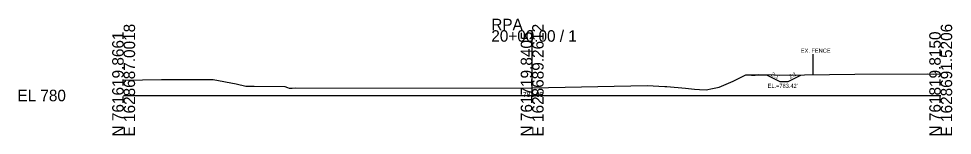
# Model space of a CAD drawing. Extents: x -26 to 203, y 990 to 7517.
# Drawn here: x -25.7 to 202.8, y 3990.3 to 4018.7 of the extents above; entities that cross this region are included whole.
import ezdxf

# ---------------------------------------------------------------- set-up
doc = ezdxf.new("R2010")
doc.units = 0
for name, color, linetype in [('Exist Cross Section Cell', 7, 'Continuous'), ('Exist XS Center Line Elevation Label', 7, 'Continuous'), ('Exist XS Ground Line', 7, 'Continuous'), ('Prop XS DDE', 7, 'Continuous'), ('Prop XS DDE Elevations', 7, 'Continuous'), ('Prop XS Side Slope Text', 7, 'Continuous')]:
    doc.layers.add(name, color=color, linetype=linetype)

msp = doc.modelspace()

# ---------------------------------------------------------------- linework, layer by layer
at = {"layer": 'Exist Cross Section Cell'}
for p, q in [((100, 4000), (100, 4015.92)), ((0, 4000), (100, 4000)), ((100, 4000), (200, 4000))]:
    msp.add_line(p, q, dxfattribs=at)
at = {"layer": 'Exist XS Ground Line'}
for p, q in [((168.79, 4005.04), (168.79, 4010.04)), ((0, 4003.73), (9.25, 4003.9)), ((9.25, 4003.9), (11.08, 4003.89)), ((11.08, 4003.89), (21.89, 4003.93)), ((21.89, 4003.93), (27.55, 4002.82)), ((149.2, 4003.46), (152.32, 4005.08)), ((152.32, 4005.08), (153.27, 4005.04)), ((153.27, 4005.04), (153.67, 4005)), ((153.67, 4005), (154.61, 4004.96)), ((154.61, 4004.96), (155.31, 4005.1)), ((155.31, 4005.1), (159.11, 4005.08)), ((159.11, 4005.08), (160.43, 4004.92)), ((160.43, 4004.92), (178.94, 4005.17)), ((178.94, 4005.17), (196.68, 4005.31)), ((196.68, 4005.31), (198.17, 4005.23)), ((198.17, 4005.23), (200, 4005.26)), ((27.55, 4002.82), (29.93, 4002.24)), ((29.93, 4002.24), (31.96, 4002.25)), ((31.96, 4002.25), (39.42, 4002.17)), ((39.42, 4002.17), (40.14, 4001.94)), ((40.14, 4001.94), (40.55, 4001.75)), ((40.55, 4001.75), (41.24, 4001.8)), ((41.24, 4001.8), (41.95, 4001.86)), ((41.95, 4001.86), (97.76, 4001.83)), ((97.76, 4001.83), (100, 4001.85)), ((100, 4001.85), (128.14, 4002.44)), ((128.14, 4002.44), (132.47, 4002.19)), ((132.47, 4002.19), (132.96, 4002.17)), ((132.96, 4002.17), (137.5, 4001.8)), ((137.5, 4001.8), (139.73, 4001.54)), ((142.57, 4001.38), (144.11, 4001.68)), ((144.11, 4001.68), (145.78, 4002.01)), ((145.78, 4002.01), (149.2, 4003.46)), ((139.73, 4001.54), (140.95, 4001.46)), ((140.95, 4001.46), (142.57, 4001.38))]:
    msp.add_line(p, q, dxfattribs=at)
at = {"layer": 'Prop XS DDE'}
for p, q in [((152.32, 4005.08), (157.32, 4005.08)), ((157.32, 4005.08), (160.64, 4003.42)), ((162.64, 4003.42), (165.78, 4005)), ((160.64, 4003.42), (162.64, 4003.42))]:
    msp.add_line(p, q, dxfattribs=at)

# ---------------------------------------------------------------- texts
at = {"layer": 'Exist Cross Section Cell'}
for s, p in [('RPA', (90, 4015.92)), ('20+00.00 / 1', (90, 4013.12)), ('EL 780', (-26, 3998.6))]:
    msp.add_text(s, height=2.8, dxfattribs=at).set_placement(p)
for s, p in [('N 761619.8661', (0, 3990)), ('E 1628687.0018', (2.8, 3990)), ('N 761719.8405', (100, 3990)), ('E 1628689.2612', (102.8, 3990)), ('N 761819.8150', (200, 3990)), ('E 1628691.5206', (202.8, 3990))]:
    msp.add_text(s, height=2.8, rotation=90, dxfattribs=at).set_placement(p)
at = {"layer": 'Exist XS Center Line Elevation Label'}
msp.add_text('781.85', height=1.2, dxfattribs=at).set_placement((97.71, 3999.65))
at = {"layer": 'Exist XS Ground Line'}
msp.add_text('EX. FENCE', height=1, dxfattribs=at).set_placement((165.75, 4010.43))
at = {"layer": 'Prop XS DDE Elevations'}
msp.add_text("EL.=783.42'", height=1, dxfattribs=at).set_placement((157.64, 4001.86))
at = {"layer": 'Prop XS Side Slope Text'}
for rotation, p in [(333.536, (158.41, 4004.84)), (27.2615, (163.13, 4004.05))]:
    msp.add_text('2:1', height=1, rotation=rotation, dxfattribs=at).set_placement(p)

doc.saveas('drawing.dxf')
